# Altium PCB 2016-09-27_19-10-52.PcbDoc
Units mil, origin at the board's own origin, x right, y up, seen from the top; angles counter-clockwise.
Board outline 3037 x 1712 mil, 4 copper layers (Top Layer, MidLayer1, MidLayer2, Bottom Layer); 17 components, 7 nets, 35 pads, 70 vias.
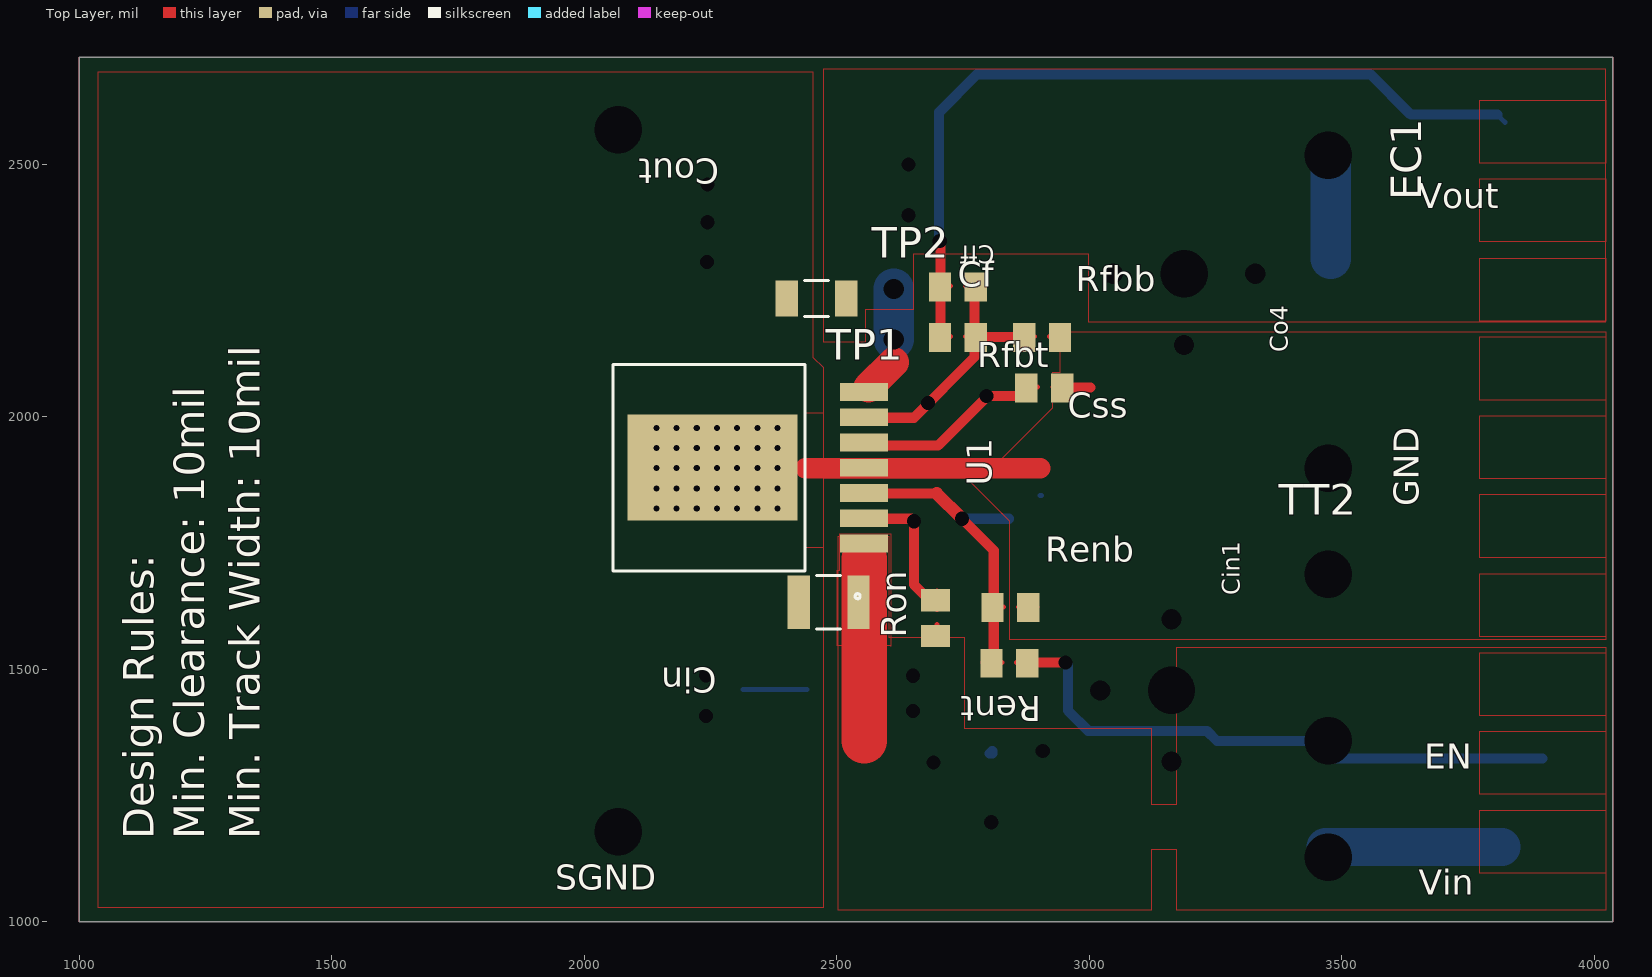
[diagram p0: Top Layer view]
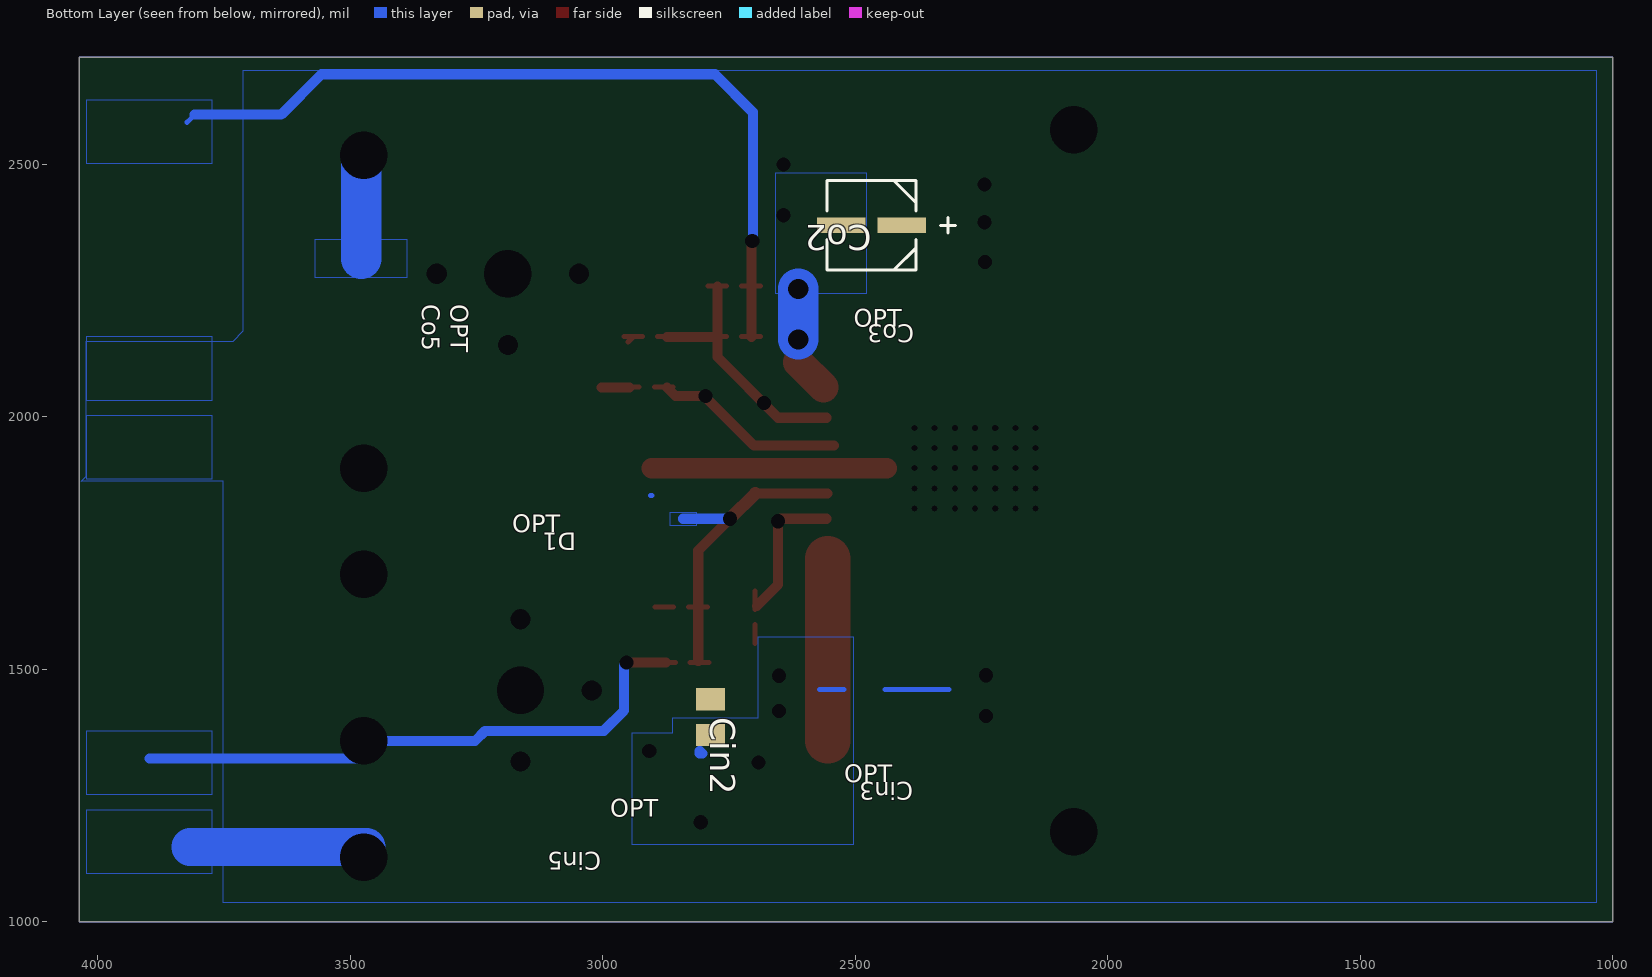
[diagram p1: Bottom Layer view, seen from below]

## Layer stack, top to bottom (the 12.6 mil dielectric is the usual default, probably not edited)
Top Layer: signal copper 1.4
Dielectric: core 12.6, FR-4, Dk 4.8
MidLayer1: signal copper 1.4
Dielectric: prepreg 12.6, FR-4, Dk 4.8
MidLayer2: signal copper 1.4
Dielectric: core 12.6, FR-4, Dk 4.8
Bottom Layer: signal copper 1.4

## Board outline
1000,1000 4037,1000 4037,2712 1000,2712

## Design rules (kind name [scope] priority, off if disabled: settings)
PlaneConnect [All] p0: scope1count=1 scope1_0_kind=Board scope1_0_value=Board scope2count=1 scope2_0_kind=Board scope2_0_value=Board commentlength=0 planeconnectstyle=Direct reliefexpansion=20 reliefentries=4 reliefconductorwidth=10 reliefairgap=10
PlaneConnect [All] p1: planeconnectstyle=Direct reliefexpansion=20 reliefentries=4 reliefconductorwidth=10 reliefairgap=10
PolygonConnect [All] p0: scope1count=1 scope1_0_kind=Board scope1_0_value=Board scope2count=1 scope2_0_kind=Board scope2_0_value=Board commentlength=0 connectstyle=Direct reliefconductorwidth=10 reliefentries=4 polygonreliefangle="90 Angle"
PolygonConnect [All] p1: connectstyle=Direct reliefconductorwidth=10 reliefentries=4 polygonreliefangle="90 Angle"

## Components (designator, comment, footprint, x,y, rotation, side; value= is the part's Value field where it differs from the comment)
Cf "" 0805#1 2740,2257 r0 top
Cin "" 1210_280 2484,1633 r180 top
Cin2 "" 0805#2 2787,1405 r90 bottom
Co2 "" CAPSMT_62_D55 2468,2379 r180 bottom
Cout "" 1206_190 2460,2234 r180 top
Css "" 0805#1 2911,2057 r0 top
EN "" TP-1502 3474,1357 r0 top
GND "" TP-1502 3481,1888 r90 top
Renb "" 0805#1 2844,1622 r0 top
Rent "" 0805#1 2842,1512 r180 top
Rfbb "" 0805#1 2907,2157 r0 top
Rfbt "" 0805#1 2740,2157 r0 top
Ron "" 0805#1 2696,1601 r90 top
SGND "" TP-1502 2064,2562 r0 top
U1 "" TZA07A 2344,1899 r90 top
Vin "" TP-1502 3474,1131 r0 top
Vout "" TP-1502 3478,2520 r0 top

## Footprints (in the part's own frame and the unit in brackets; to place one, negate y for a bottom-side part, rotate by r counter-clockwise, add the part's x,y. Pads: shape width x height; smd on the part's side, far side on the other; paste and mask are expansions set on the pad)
0805#1 [mil]
  rect 44x57 smd: 1(-35.5,0) 2(35.5,0)
0805#2 [mil]
  rect 44x57 smd: 1(35.5,0) 2(-35.5,0)
1206_190 [mil]
  rect 44x71 smd: 1(-59,0) 2(59,0)
  silkscreen extent -24,-36 24,36
1210_280 [mil]
  rect 44x106 smd: 1(-59,0) 2(59,0)
  silkscreen extent -24,-53 24,53
CAPSMT_62_D55 [mil]
  rect 96x31 smd: 1(59.5,0) 2(-59.5,0)
  silkscreen extent -89,-89 166,89
TP-1502 [mil]
  round 65 / inner round 0 / far side round 65 hole 32: 1(0,0)
TZA07A [mil]
  rect 35x95 smd: 1(-150,-210.25) 2(-100,-210.25) 3(-50,-210.25) 4(0,-210.25) 5(50,-210.25) 6(100,-210.25) 7(150,-210.25)
  rect 210x336 smd: 8(0,89.75)
  silkscreen extent -259,-202 204,287

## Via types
v1: diameter 0, hole 12, Top Layer to Bottom Layer, 35 vias
v2: diameter 0, hole 28, Top Layer to Bottom Layer, 18 vias
v3: diameter 0, hole 94, Top Layer to Bottom Layer, 9 vias
v4: diameter 0, hole 40, Top Layer to Bottom Layer, 8 vias

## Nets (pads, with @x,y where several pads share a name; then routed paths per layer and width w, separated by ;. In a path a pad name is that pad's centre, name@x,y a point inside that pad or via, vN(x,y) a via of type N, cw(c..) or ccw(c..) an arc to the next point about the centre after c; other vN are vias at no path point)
0: Cin2.1 Cin.2 Co2.1 Cout.2 Css.2 GND.1 Renb.2 Rfbb.2 SGND.1 U1.4 U1.8 | length 775.1
  Top Layer w10: Renb.2@2860,1623.5 Renb.2@2897,1623.5 ; Rfbb.2@2921,2158.5 Rfbb.2@2958,2158.5 ; Css.2@2928,2058.5 Css.2@2965,2058.5 ; Rfbb.2@2940,2158 Rfbb.2@2950,2148
  Top Layer w20: Css.2@2947,2058 3003,2058
  Top Layer w40: 2438,1898 2903,1898
  Bottom Layer w10: 2315,1460 2441,1460 ; 2903,1844 2906,1844
  other v1: 2143,1818 2183,1818 2223,1818 2263,1818 2303,1818 2343,1818 2383,1818 2143,1858 2183,1858 2223,1858 2263,1858 2303,1858 2343,1858 2383,1858 2143,1898 2183,1898 2223,1898 2263,1898 2303,1898 2343,1898 2383,1898 2143,1938 2183,1938 2223,1938 2263,1938 2303,1938 2343,1938 2383,1938 2143,1978 2183,1978 2223,1978 2263,1978 2303,1978 2343,1978 2383,1978
  other v2: 2241,1407 2241,1488 2243,2306 2244,2385 2244,2460
  other v3: 2068,1178 3473,1688 3473,1898 2068,2568
  other v4: 3163,1317 3022,1458 3163,1599 3188,2142 3047,2283 3329,2283
1: Renb.1 Rent.2 U1.3 | length 698.8
  Top Layer w10: Rent.2@2790,1513.5 Rent.2@2827,1513.5 ; Renb.1@2793,1623.5 Renb.1@2830,1623.5
  Top Layer w20: U1.3@2555,1848 2557,1848 2698,1848 2688,1848 ; v2(2748,1798) 2811,1735 2811,1623 Rent.2@2811,1516
  Top Layer w25: 2698,1848 v2(2748,1798)
  Bottom Layer w20: v2(2748,1798) 2841,1798
2: Cin2.2 Cin.1 EN.1 Rent.1 Ron.1 U1.1 Vin.1 | length 2009.6
  Top Layer w10: Ron.1@2698.5,1551 2698.5,1588 ; Rent.1@2856,1513.5 Rent.1@2893,1513.5
  Top Layer w20: Rent.1@2875,1513 v2(2953,1513)
  Top Layer w90: 2555,1358 2555,1719
  Bottom Layer w10: 2523,1460 2571,1460 ; 3822,1178 3823,1177
  Bottom Layer w20: 2803,1333 2808,1333 2808,1338 ; v2(2953,1513) 2958,1508 2958,1418 2998,1378 3233,1378 3253,1358 v3(3473,1358) ; Vin.1@3458,1103 Vin.1@3473,1118 ; 3468,1323 3898,1323
  Bottom Layer w75: Vin.1@3468,1148 3817,1148
  other v2: 2806,1197 2692,1315 2908,1338 2651,1417 2651,1487
  other v3: 3473,1128 3163,1458
3: Cf.1 Co2.2 Cout.1 Rfbt.1 U1.7 Vout.1 | length 2112.6
  Top Layer w10: U1.7@2563,2048 U1.7@2563,2058 ; 2613,2108 2613,2118 ; Rfbt.1@2688,2158.5 Rfbt.1@2725,2158.5 ; Cf.1@2688,2258.5 Cf.1@2725,2258.5 ; 2698,2348 2706,2340
  Top Layer w20: Rfbt.1@2706,2158 2706,2258 2706,2340
  Top Layer w60: U1.7@2563,2058 2613,2108
  Bottom Layer w10: 3808,2598 3823,2583 3813,2593
  Bottom Layer w20: 2703,2353 2703,2603 2778,2678 3557,2678 3637,2598 3808,2598
  Bottom Layer w80: v4(2613,2153) v4(2613,2253) ; 3478,2313 Vout.1@3478,2513
  other v2: 2704,2348 2642,2399 2642,2499
  other v3: 3188,2283 3473,2518
4: Cf.2 Rfbb.1 Rfbt.2 U1.6 | length 616.7
  Top Layer w10: Rfbt.2@2755,2158.5 Rfbt.2@2792,2158.5 ; Cf.2@2755,2258.5 Cf.2@2792,2258.5 ; Rfbb.1@2855,2158.5 Rfbb.1@2892,2158.5
  Top Layer w20: U1.6@2557,1998 2653,1998 2773,2118 Rfbt.2@2773,2158 ; Cf.2@2773,2258 Rfbt.2@2773,2158 ; Rfbb.1@2873,2158 Rfbt.2@2773,2158
  other v2: 2681,2027
5: Css.1 U1.5 | length 423.3
  Top Layer w10: U1.5@2557,1948 U1.5@2562,1943 ; Css.1@2861,2058.5 2898,2058.5
  Top Layer w20: U1.5@2542,1943 2701,1943 2798,2040 ; v2(2797,2041) 2856,2041 Css.1@2873,2058
6: Ron.2 U1.2 | length 313.1
  Top Layer w10: Ron.2@2698.5,1618 Ron.2@2698.5,1655
  Top Layer w20: U1.2@2557,1798 2648,1798 ; v2(2653,1793) 2653,1668 Ron.2@2695,1625

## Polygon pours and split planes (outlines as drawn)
2 on Top Layer " " (solid, pour order 0): 2506,1768 2607,1768 2607,1545 2606,1546 2501,1546 2501,1696 2506,1696
2 on Top Layer " " (solid, pour order 1): 3773,1096 3773,1221 4023,1221 4023,1096
2 on Top Layer " " (solid, pour order 2): 3773,1252 3773,1377 4023,1377 4023,1252
2 on Top Layer " " (solid, pour order 3): 3773,1408 3773,1533 4023,1533 4023,1408
3 on Top Layer " " (solid, pour order 4): 3773,2189 3773,2314 4023,2314 4023,2189
3 on Top Layer " " (solid, pour order 5): 3773,2346 3773,2471 4023,2471 4023,2346
3 on Top Layer " " (solid, pour order 6): 3773,2502 3773,2627 4023,2627 4023,2502
2 on Top Layer " " (solid, pour order 19): 2503,1023 2503,1763 2603,1763 2603,1563 2753,1563 2753,1383 3123,1383 3123,1233 3173,1233 3173,1543 4023,1543 4023,1023 3173,1023 3173,1143 3123,1143 3123,1023
3 on Top Layer " " (solid, pour order 20): 2473,2148 2558,2148 2558,2213 2653,2213 2653,2323 2998,2323 2998,2188 4023,2188 4023,2688 2473,2688
0 on Top Layer " " (solid, pour order 21): 2438,1740 2438,2008 2473,2008 2473,1740
0 on Top Layer " " (solid, pour order 22): 3773,1564 3773,1689 4023,1689 4023,1564
0 on Top Layer " " (solid, pour order 23): 3773,1721 3773,1846 4023,1846 4023,1721
0 on Top Layer " " (solid, pour order 24): 3773,1877 3773,2002 4023,2002 4023,1877
0 on Top Layer " " (solid, pour order 25): 3773,2033 3773,2158 4023,2158 4023,2033
0 on Top Layer " " (solid, pour order 31): 1038,1028 1038,2683 2453,2683 2453,2118 2473,2098 2473,1918 2828,1918 2928,2018 2928,2088 2943,2088 2943,2168 4023,2168 4023,1558 2843,1558 2843,1793 2758,1878 2473,1878 2473,1028
2 on Bottom Layer " " (solid, pour order 7): 3773,1096 3773,1221 4023,1221 4023,1096
2 on Bottom Layer " " (solid, pour order 8): 3773,1252 3773,1377 4023,1377 4023,1252
3 on Bottom Layer " " (solid, pour order 14): 3773,2502 3773,2627 4023,2627 4023,2502
3 on Bottom Layer " " (solid, pour order 15): 3387,2276 3387,2350 3570,2350 3570,2276
1 on Bottom Layer " " (solid, pour order 16): 2814,1785 2814,1810 2867,1810 2867,1785
2 on Bottom Layer " " (solid, pour order 17): 2503,1153 2503,1563 2693,1563 2693,1403 2863,1403 2863,1373 2943,1373 2943,1153
3 on Bottom Layer " " (solid, pour order 18): 2478,2483 2478,2243 2658,2243 2658,2483
0 on Bottom Layer " " (solid, pour order 26): 3773,1877 3773,2002 4023,2002 4023,1877
0 on Bottom Layer " " (solid, pour order 27): 3773,2033 3773,2158 4023,2158 4023,2033
0 on Bottom Layer " " (solid, pour order 30): 1033,2686 1033,1038 3752,1038 3752,1872 4033,1872 4023,1882 4023,2149 3732,2149 3712,2170 3712,2686
0 on MidLayer2 " " (solid, pour order 28): 3753,1033 3753,1873 3753,2143 3713,2143 3713,2693 1033,2693 1033,1033
0 on MidLayer1 " " (solid, pour order 29): 1033,1033 3753,1033 3753,1873 4023,1873 4023,2143 3713,2143 3713,2693 1033,2693

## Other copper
Multi-Layer:
  the board outline again, w1

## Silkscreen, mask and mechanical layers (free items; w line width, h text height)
Top Overlay:
  text "EC1" at 3658,2429 h60 r90
  text "Cff" at 2813,2338 h35 r180
  text "TP2" at 2569,2315 h60
  text "Co4" at 3393,2128 h35 r90
  text "TP1" at 2478,2113 h60
  text "TT2" at 3375,1806 h60
  text "Cin1" at 3298,1646 h35 r90
  text "Design Rules:" at 1148,1163 h60 r90
  text "Min. Clearance: 10mil" at 1248,1163 h60 r90
  text "Min. Track Width: 10mil" at 1358,1163 h60 r90
Bottom Overlay:
  text "OPT" at 3301,2223 h35 r90
  text "Co5" at 3358,2223 h35 r90
  text "Co3" at 2383,2182 h35 r180
  text "OPT" at 2503,2178 h35
  text "OPT" at 3179,1771 h35
  text "D1" at 3053,1770 h35 r180
  text "Cin3" at 2385,1276 h35 r180
  text "OPT" at 2522,1276 h35
  text "OPT" at 2985,1208 h35
  text "Cin5" at 3003,1138 h35 r180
